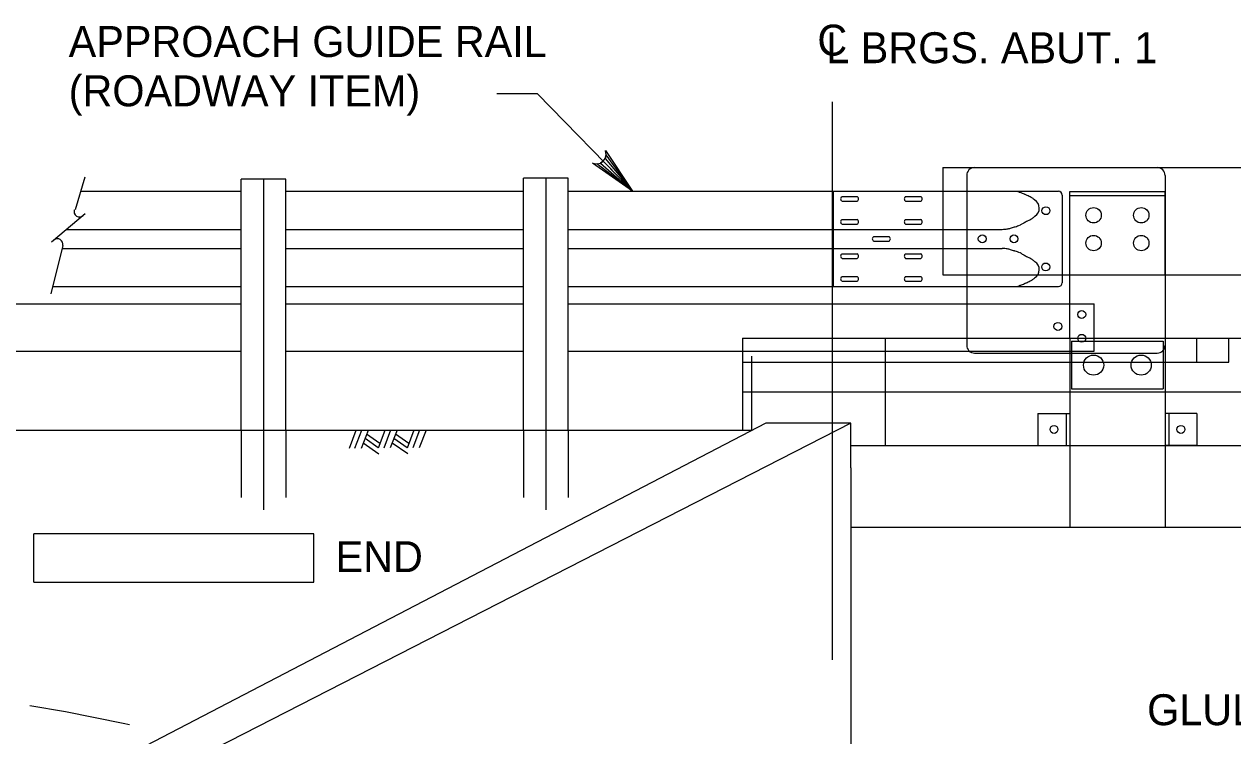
# Model space of a CAD drawing. Extents: x 638268 to 640277, y 295465 to 298435.
# Drawn here: x 638488.1 to 638605.4, y 298043.9 to 298112.9 of the extents above; entities that cross this region are included whole.
import ezdxf

# ---------------------------------------------------------------- set-up
doc = ezdxf.new("R2010")
doc.units = 0
for name, color, linetype in [('2', 7, 'Continuous'), ('3', 7, 'Continuous'), ('4', 7, 'Continuous'), ('52', 7, 'Continuous'), ('8', 7, 'Continuous'), ('Level 25', 7, 'Continuous')]:
    doc.layers.add(name, color=color, linetype=linetype)

msp = doc.modelspace()

# ---------------------------------------------------------------- linework, layer by layer
at = {"layer": '2'}
for p, q in [((638577.23, 298099.02), (638577.23, 298096.71)), ((638577.23, 298099.02), (638750.23, 298099.02)), ((638493.6, 298096.72), (638509.18, 298096.72)), ((638513.5, 298096.72), (638536.57, 298096.72)), ((638540.9, 298096.72), (638566.58, 298096.72)), ((638566.58, 298096.72), (638566.58, 298087.48)), ((638566.64, 298096.72), (638577.23, 298096.72)), ((638577.23, 298096.72), (638588.44, 298096.72)), ((638577.23, 298096.7), (638577.23, 298088.62)), ((638588.81, 298096.35), (638588.81, 298087.85)), ((638589.55, 298096.7), (638598.78, 298096.7)), ((638589.55, 298082.46), (638589.55, 298096.7)), ((638589.55, 298096.32), (638598.78, 298096.32)), ((638598.78, 298088.62), (638598.78, 298096.7)), ((638567.45, 298096.21), (638568.92, 298096.21)), ((638567.45, 298095.75), (638568.92, 298095.75)), ((638573.62, 298096.21), (638575.1, 298096.21)), ((638573.62, 298095.75), (638575.1, 298095.75)), ((638567.45, 298093.99), (638568.92, 298093.99)), ((638573.62, 298093.99), (638575.1, 298093.99)), ((638492.25, 298093.02), (638509.18, 298093.02)), ((638513.5, 298093.02), (638536.57, 298093.02)), ((638540.9, 298093.02), (638577.23, 298093.02)), ((638567.45, 298093.53), (638568.92, 298093.53)), ((638573.62, 298093.53), (638575.1, 298093.53)), ((638577.23, 298093.02), (638582.98, 298093.02)), ((638570.53, 298092.33), (638572.01, 298092.33)), ((638570.53, 298091.87), (638572.01, 298091.87)), ((638491.81, 298091.18), (638509.18, 298091.18)), ((638513.5, 298091.18), (638536.57, 298091.18)), ((638540.9, 298091.18), (638577.23, 298091.18)), ((638567.45, 298090.67), (638568.92, 298090.67)), ((638573.62, 298090.67), (638575.1, 298090.67)), ((638577.23, 298091.18), (638582.98, 298091.18)), ((638567.45, 298090.2), (638568.92, 298090.2)), ((638573.62, 298090.2), (638575.1, 298090.2)), ((638567.45, 298088.45), (638568.92, 298088.45)), ((638573.62, 298088.45), (638575.1, 298088.45)), ((638577.23, 298088.62), (638579.54, 298088.62)), ((638579.54, 298088.62), (638589.55, 298088.62)), ((638589.55, 298088.62), (638598.78, 298088.62)), ((638598.78, 298088.62), (638598.78, 298082.46)), ((638598.78, 298088.62), (638637.2, 298088.62)), ((638490.88, 298087.48), (638509.18, 298087.48)), ((638513.5, 298087.48), (638536.57, 298087.48)), ((638540.9, 298087.48), (638579.54, 298087.48)), ((638567.45, 298087.99), (638568.92, 298087.99)), ((638573.62, 298087.99), (638575.1, 298087.99)), ((638579.54, 298087.48), (638588.44, 298087.48)), ((638486.95, 298085.82), (638509.18, 298085.82)), ((638513.5, 298085.82), (638536.57, 298085.82)), ((638540.9, 298085.82), (638579.54, 298085.82)), ((638579.54, 298085.82), (638591.89, 298085.82)), ((638591.89, 298081.2), (638591.89, 298085.82)), ((638557.8, 298082.46), (638589.55, 298082.46)), ((638557.8, 298082.46), (638557.8, 298073.51)), ((638571.65, 298082.46), (638571.65, 298072.07)), ((638579.54, 298082.46), (638579.54, 298081.8)), ((638589.55, 298082.46), (638598.78, 298082.46)), ((638589.55, 298082.46), (638589.55, 298064.14)), ((638589.71, 298082.18), (638589.71, 298077.56)), ((638589.71, 298082.18), (638598.59, 298082.18)), ((638598.59, 298082.18), (638598.59, 298077.56)), ((638598.78, 298082.46), (638637.2, 298082.46)), ((638598.78, 298082.46), (638598.78, 298064.14)), ((638601.86, 298080.15), (638601.86, 298082.46)), ((638604.95, 298080.15), (638604.95, 298082.46)), ((638485.55, 298081.2), (638509.18, 298081.2)), ((638513.5, 298081.2), (638536.57, 298081.2)), ((638540.9, 298081.2), (638557.8, 298081.2)), ((638557.8, 298081.2), (638591.89, 298081.2)), ((638557.8, 298080.15), (638604.95, 298080.15)), ((638589.71, 298077.56), (638598.59, 298077.56)), ((638557.8, 298077.26), (638589.55, 298077.26)), ((638589.55, 298077.26), (638598.78, 298077.26)), ((638598.78, 298077.26), (638614.94, 298077.26)), ((638586.45, 298075.16), (638589.55, 298075.16)), ((638586.45, 298075.16), (638586.45, 298072.07)), ((638589.18, 298075.16), (638589.18, 298072.07)), ((638589.55, 298075.16), (638589.55, 298072.07)), ((638601.87, 298075.16), (638598.78, 298075.16)), ((638598.78, 298075.16), (638598.78, 298072.07)), ((638599.15, 298075.16), (638599.15, 298072.07)), ((638601.87, 298075.16), (638601.87, 298072.07)), ((638586.45, 298072.07), (638589.55, 298072.07)), ((638589.55, 298072.07), (638598.78, 298072.07)), ((638601.87, 298072.07), (638598.78, 298072.07)), ((638598.78, 298072.07), (638637.2, 298072.07)), ((638601.87, 298072.07), (638598.78, 298072.07))]:
    msp.add_line(p, q, dxfattribs=at)
for centre, radius in [((638587.23, 298094.84), 0.385), ((638591.85, 298094.4), 0.748), ((638596.47, 298094.4), 0.748), ((638581.05, 298092.11), 0.385), ((638584.13, 298092.11), 0.385), ((638591.85, 298091.7), 0.748), ((638596.47, 298091.7), 0.748), ((638587.21, 298089.38), 0.385), ((638590.7, 298084.77), 0.385), ((638588.39, 298083.61), 0.385), ((638590.7, 298082.46), 0.385), ((638591.85, 298079.86), 0.978), ((638596.46, 298079.86), 0.978), ((638588.01, 298073.62), 0.385), ((638600.32, 298073.62), 0.385)]:
    msp.add_circle(centre, radius, dxfattribs=at)
for centre, radius, start, end in [((638581.4, 298086.99), 10.17, 71.5066, 72.9766), ((638584.03, 298094.85), 1.88, 68.0907, 71.5066), ((638560.58, 298036.55), 64.73, 67.6851, 68.0907), ((638582.91, 298090.94), 5.93, 66.3453, 67.6851), ((638584.32, 298094.16), 2.42, 63.4251, 66.3453), ((638571.17, 298067.88), 31.8, 62.6202, 63.4251), ((638588.44, 298096.35), 0.369, 0, 90), ((638567.58, 298095.98), 0.269, 120.8559, 239.1441), ((638568.79, 298095.98), 0.269, 300.8559, 59.1441), ((638573.76, 298095.98), 0.269, 120.8559, 239.1441), ((638574.96, 298095.98), 0.269, 300.8559, 59.1441), ((638585.36, 298095.27), 0.955, 54.6771, 62.6202), ((638583.36, 298092.45), 4.42, 50.9849, 54.6771), ((638585.67, 298095.09), 0.916, 301.3851, 59.6468), ((638567.58, 298093.76), 0.269, 120.8559, 239.1441), ((638568.79, 298093.76), 0.269, 300.8559, 59.1441), ((638573.76, 298093.76), 0.269, 120.8559, 239.1441), ((638574.96, 298093.76), 0.269, 300.8559, 59.1441), ((638398.16, 298439.15), 392.83, 298.4725, 298.525), ((638585.23, 298094.96), 1.09, 298.525, 306.8818), ((638582.92, 298098.04), 4.94, 306.8818, 310.7993), ((638582.75, 298098.05), 5.03, 272.6429, 278.367), ((638583.16, 298095.21), 2.16, 278.367, 287.1115), ((638556.74, 298181.03), 91.96, 287.1115, 287.3611), ((638583.24, 298096.26), 3.14, 287.3611, 288.7111), ((638578.42, 298110.5), 18.18, 288.7111, 290.2329), ((638584.49, 298094.05), 0.644, 290.2329, 298.3215), ((638574.61, 298112.37), 21.45, 298.3215, 298.7501), ((638640.28, 297992.66), 115.08, 118.565, 118.7501), ((638645.68, 297982.76), 126.36, 118.4725, 118.565), ((638570.66, 298092.1), 0.269, 120.8559, 239.1441), ((638571.87, 298092.1), 0.269, 300.8559, 59.1441), ((638567.58, 298090.44), 0.269, 120.8559, 239.1441), ((638568.79, 298090.44), 0.269, 300.8559, 59.1441), ((638573.76, 298090.44), 0.269, 120.8559, 239.1441), ((638574.96, 298090.44), 0.269, 300.8559, 59.1441), ((638582.75, 298086.15), 5.03, 81.633, 87.3571), ((638583.16, 298088.99), 2.16, 72.8885, 81.633), ((638556.74, 298003.16), 91.96, 72.6389, 72.8885), ((638583.24, 298087.94), 3.14, 71.2889, 72.6389), ((638578.42, 298073.7), 18.18, 69.7671, 71.2889), ((638584.49, 298090.15), 0.644, 61.6785, 69.7671), ((638574.61, 298071.83), 21.45, 61.2499, 61.6785), ((638640.28, 298191.53), 115.08, 241.2499, 241.435), ((638645.68, 298201.44), 126.36, 241.435, 241.5275), ((638398.16, 297745.04), 392.83, 61.475, 61.5275), ((638585.23, 298089.23), 1.09, 53.1182, 61.475), ((638582.92, 298086.15), 4.94, 49.2007, 53.1182), ((638585.67, 298089.11), 0.916, 300.3532, 58.6149), ((638567.58, 298088.22), 0.269, 120.8559, 239.1441), ((638568.79, 298088.22), 0.269, 300.8559, 59.1441), ((638573.76, 298088.22), 0.269, 120.8559, 239.1441), ((638574.96, 298088.22), 0.269, 300.8559, 59.1441), ((638571.17, 298116.32), 31.8, 296.5749, 297.3798), ((638585.36, 298088.93), 0.955, 297.3798, 305.3229), ((638583.36, 298091.75), 4.42, 305.3229, 309.0151), ((638581.4, 298097.2), 10.17, 287.0234, 288.4934), ((638584.03, 298089.35), 1.88, 288.4934, 291.9093), ((638560.58, 298147.65), 64.73, 291.9093, 292.3149), ((638582.91, 298093.26), 5.93, 292.3149, 293.6547), ((638584.32, 298090.04), 2.42, 293.6547, 296.5749), ((638588.44, 298087.85), 0.369, 270, 0)]:
    msp.add_arc(centre, radius, start, end, dxfattribs=at)
at = {"layer": '3'}
for p, q in [((638513.5, 298097.9), (638509.18, 298097.9)), ((638509.18, 298073.51), (638509.18, 298097.9)), ((638511.34, 298097.9), (638511.34, 298065.82)), ((638513.5, 298073.51), (638513.5, 298097.9)), ((638540.9, 298097.98), (638536.57, 298097.98)), ((638536.57, 298073.51), (638536.57, 298097.98)), ((638538.73, 298097.98), (638538.73, 298065.82)), ((638540.9, 298073.51), (638540.9, 298097.98)), ((638494.06, 298094.54), (638490.8, 298091.8)), ((638491.88, 298091.46), (638490.71, 298086.79)), ((638558.69, 298073.51), (638558.69, 298080.72)), ((638560.07, 298074.23), (638494.94, 298040.35)), ((638568.29, 298074.23), (638502.08, 298040.35)), ((638568.29, 298074.23), (638560.07, 298074.23)), ((638568.29, 298069.91), (638568.29, 298074.23)), ((638558.69, 298073.51), (638480.78, 298073.51)), ((638558.69, 298073.51), (638493.49, 298073.51)), ((638509.18, 298073.51), (638509.18, 298067.03)), ((638513.5, 298073.51), (638513.5, 298067.03)), ((638520.3, 298073.51), (638519.64, 298071.76)), ((638520.3, 298073.51), (638519.64, 298071.76)), ((638520.85, 298073.52), (638520.18, 298071.76)), ((638520.85, 298073.52), (638520.18, 298071.76)), ((638521.49, 298073.53), (638520.82, 298071.78)), ((638521.49, 298073.53), (638520.82, 298071.78)), ((638521.35, 298073.19), (638522.64, 298072.29)), ((638521.35, 298073.19), (638522.64, 298072.29)), ((638523.11, 298073.53), (638522.46, 298071.8)), ((638523.11, 298073.53), (638522.46, 298071.8)), ((638523.66, 298073.54), (638523.01, 298071.81)), ((638523.66, 298073.54), (638523.01, 298071.81)), ((638524.3, 298073.54), (638523.64, 298071.82)), ((638524.3, 298073.54), (638523.64, 298071.82)), ((638524.16, 298073.2), (638525.45, 298072.3)), ((638524.16, 298073.2), (638525.45, 298072.3)), ((638525.92, 298073.54), (638525.27, 298071.81)), ((638525.92, 298073.54), (638525.27, 298071.81)), ((638526.47, 298073.55), (638525.82, 298071.82)), ((638526.47, 298073.55), (638525.82, 298071.82)), ((638527.11, 298073.55), (638526.45, 298071.83)), ((638527.11, 298073.55), (638526.45, 298071.83)), ((638536.57, 298073.51), (638536.57, 298067.03)), ((638540.9, 298073.51), (638540.9, 298067.03)), ((638521.02, 298072.31), (638522.52, 298071.27)), ((638521.02, 298072.31), (638522.52, 298071.27)), ((638521.19, 298072.76), (638522.48, 298071.86)), ((638521.19, 298072.76), (638522.48, 298071.86)), ((638523.83, 298072.32), (638525.33, 298071.28)), ((638523.83, 298072.32), (638525.33, 298071.28)), ((638524, 298072.77), (638525.29, 298071.88)), ((638524, 298072.77), (638525.29, 298071.88)), ((638568.29, 298072.07), (638589.55, 298072.07)), ((638568.29, 298069.91), (638568.29, 298007.18)), ((638568.29, 298064.14), (638747.07, 298064.14))]:
    msp.add_line(p, q, dxfattribs=at)
for centre, start, end in [((638493.5, 298094.77), 162.1496, 312.1496), ((638491.36, 298091.58), 130.0028, 130.0168), ((638491.36, 298091.58), 347.4782, 130.0168)]:
    msp.add_arc(centre, 0.533, start, end, dxfattribs=at)
at = {"layer": '4'}
for p, q in [((638537.91, 298106.18), (638533.97, 298106.18)), ((638547.12, 298096.72), (638537.91, 298106.18)), ((638566.48, 298105.41), (638566.48, 298051.26)), ((638516.23, 298063.5), (638489.08, 298063.5)), ((638489.08, 298058.79), (638489.08, 298063.5)), ((638516.23, 298058.79), (638516.23, 298063.5)), ((638489.08, 298058.79), (638516.23, 298058.79))]:
    msp.add_line(p, q, dxfattribs=at)
msp.add_lwpolyline([(638547.12, 298096.72), (638543.25, 298099.46), (638543.68, 298099.38), (638544.03, 298099.46), (638544.29, 298099.64), (638544.48, 298099.9), (638544.58, 298100.25), (638544.51, 298100.68), (638547.12, 298096.72), (638544.58, 298100.25), (638544.48, 298099.9), (638547.12, 298096.72), (638544.29, 298099.64), (638544.03, 298099.46), (638547.12, 298096.72), (638543.68, 298099.38)], dxfattribs=at)
at = {"layer": '52'}
msp.add_line((638494.01, 298098.08), (638493.07, 298094.91), dxfattribs=at)
at = {"layer": '8'}
for p, q in [((638492.15, 298046.23), (638488.69, 298046.8)), ((638497.74, 298045.11), (638492.15, 298046.23)), ((638498.35, 298044.96), (638497.74, 298045.11))]:
    msp.add_line(p, q, dxfattribs=at)
at = {"layer": 'Level 25'}
for p, q in [((638580.31, 298099.02), (638598.01, 298099.02)), ((638579.54, 298098.25), (638579.54, 298096.71)), ((638598.78, 298098.25), (638598.78, 298096.7)), ((638579.54, 298096.71), (638579.54, 298087.47)), ((638598.78, 298096.7), (638598.78, 298081.8)), ((638579.54, 298087.47), (638579.54, 298082.46)), ((638580.31, 298081.03), (638598.01, 298081.03))]:
    msp.add_line(p, q, dxfattribs=at)
for centre, start, end in [((638580.31, 298098.25), 90, 180), ((638598.01, 298098.25), 0, 90), ((638580.31, 298081.8), 180, 270), ((638598.01, 298081.8), 270, 0)]:
    msp.add_arc(centre, 0.77, start, end, dxfattribs=at)

# ---------------------------------------------------------------- texts
at = {"layer": '4'}
for s, p in [('APPROACH GUIDE RAIL', (638492.45, 298109.75)), ('C', (638565.06, 298109.89)), ('L BRGS. ABUT. 1', (638565.92, 298109.15)), ('(ROADWAY ITEM)', (638492.45, 298104.97)), ('END', (638518.33, 298059.78)), ('GLULAM STIFFENER BEAM (TYP.)', (638597.04, 298044.93))]:
    msp.add_text(s, height=3, dxfattribs=at).set_placement(p)

doc.saveas('drawing.dxf')
